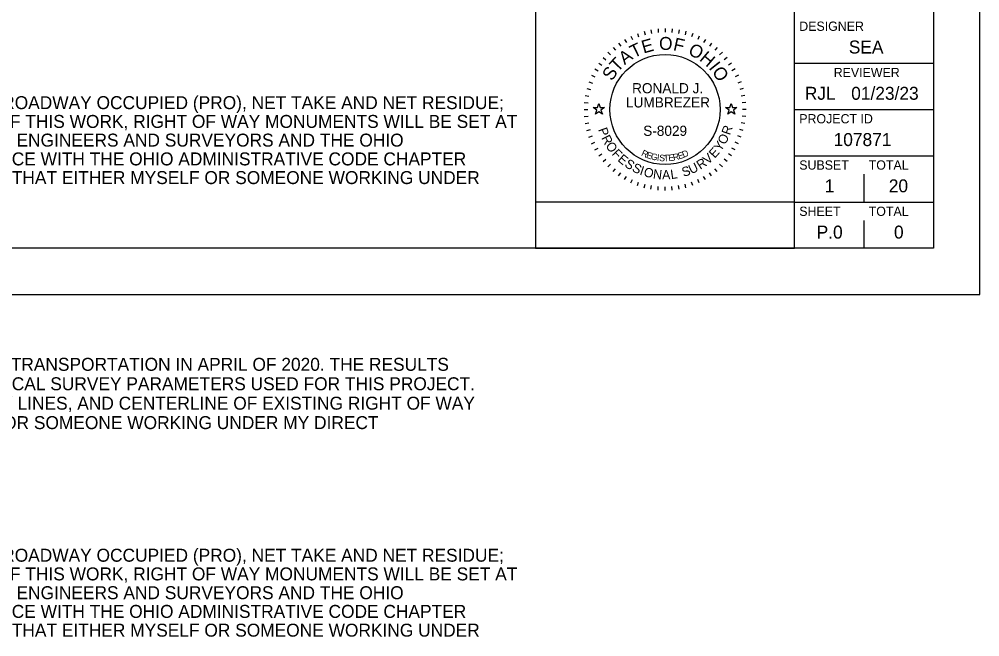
# Model space of a CAD drawing. Extents: x 0 to 39.3, y -3.9 to 22.
# Drawn here: x 23.62 to 34, y -3.7 to 2.98 of the extents above; entities that cross this region are included whole.
import ezdxf

# ---------------------------------------------------------------- set-up
doc = ezdxf.new("R2010")
doc.units = 0
for name, color, linetype in [('Default', 7, 'Continuous'), ('SH_Border', 7, 'Continuous'), ('SH_Cut_Line', 7, 'Continuous'), ('SH_Data', 7, 'Continuous'), ('SH_Text', 7, 'Continuous')]:
    doc.layers.add(name, color=color, linetype=linetype)

msp = doc.modelspace()

# ---------------------------------------------------------------- linework, layer by layer
at = {"layer": 'Default'}
for points in [[(29.824, 2.02), (29.871, 2.02), (29.885, 2.065), (29.899, 2.02), (29.946, 2.02), (29.908, 1.992), (29.923, 1.948), (29.885, 1.975), (29.847, 1.948), (29.862, 1.992)], [(31.254, 2.02), (31.301, 2.02), (31.315, 2.065), (31.329, 2.02), (31.376, 2.02), (31.338, 1.992), (31.353, 1.948), (31.315, 1.975), (31.277, 1.948), (31.292, 1.992)]]:
    msp.add_lwpolyline(points, close=True, dxfattribs=at)
at = {"layer": 'SH_Border'}
for p, q in [((32, 0.5), (32, 21.5)), ((32, 2.5), (33.5, 2.5)), ((32, 2), (33.5, 2)), ((32, 1.5), (33.5, 1.5)), ((32, 1), (33.5, 1))]:
    msp.add_line(p, q, dxfattribs=at)
msp.add_lwpolyline([(1.5, 21.5), (33.5, 21.5), (33.5, 0.5), (1.5, 0.5)], close=True, dxfattribs=at)
at = {"layer": 'SH_Cut_Line'}
msp.add_lwpolyline([(0, 0), (34, 0), (34, 22), (0, 22)], close=True, dxfattribs=at)
at = {"layer": 'SH_Data'}
for p, q in [((29.2, 3.75), (29.2, 0.5)), ((32, 0.5), (32, 3.75)), ((30.301, 2.822), (30.314, 2.785)), ((30.374, 2.845), (30.384, 2.807)), ((30.448, 2.862), (30.455, 2.822)), ((30.524, 2.872), (30.527, 2.832)), ((30.6, 2.875), (30.6, 2.835)), ((30.676, 2.872), (30.673, 2.832)), ((30.752, 2.862), (30.745, 2.822)), ((30.826, 2.845), (30.816, 2.807)), ((30.899, 2.822), (30.886, 2.785)), ((30.098, 2.717), (30.121, 2.684)), ((30.163, 2.758), (30.183, 2.723)), ((30.23, 2.793), (30.247, 2.757)), ((30.97, 2.793), (30.953, 2.757)), ((31.037, 2.758), (31.017, 2.723)), ((31.102, 2.717), (31.079, 2.684)), ((29.981, 2.619), (30.01, 2.59)), ((30.038, 2.67), (30.063, 2.64)), ((31.162, 2.67), (31.137, 2.64)), ((31.219, 2.619), (31.19, 2.59)), ((29.883, 2.502), (29.916, 2.479)), ((29.93, 2.562), (29.96, 2.537)), ((31.27, 2.562), (31.24, 2.537)), ((31.317, 2.502), (31.284, 2.479)), ((29.842, 2.438), (29.877, 2.418)), ((31.358, 2.438), (31.323, 2.418)), ((29.778, 2.299), (29.815, 2.286)), ((29.807, 2.37), (29.843, 2.353)), ((31.393, 2.37), (31.357, 2.353)), ((31.422, 2.299), (31.385, 2.286)), ((29.755, 2.226), (29.793, 2.216)), ((31.445, 2.226), (31.407, 2.216)), ((29.728, 2.076), (29.768, 2.073)), ((29.738, 2.152), (29.778, 2.145)), ((31.462, 2.152), (31.422, 2.145)), ((31.472, 2.076), (31.432, 2.073)), ((29.725, 2), (29.765, 2)), ((31.475, 2), (31.435, 2)), ((29.728, 1.924), (29.768, 1.927)), ((31.472, 1.924), (31.432, 1.927)), ((29.738, 1.848), (29.778, 1.855)), ((29.755, 1.774), (29.793, 1.784)), ((31.445, 1.774), (31.407, 1.784)), ((31.462, 1.848), (31.422, 1.855)), ((29.778, 1.701), (29.815, 1.714)), ((31.422, 1.701), (31.385, 1.714)), ((29.807, 1.63), (29.843, 1.647)), ((29.842, 1.563), (29.877, 1.583)), ((31.358, 1.563), (31.323, 1.583)), ((31.393, 1.63), (31.357, 1.647)), ((29.883, 1.498), (29.916, 1.521)), ((29.93, 1.438), (29.96, 1.463)), ((31.27, 1.438), (31.24, 1.463)), ((31.317, 1.498), (31.284, 1.521)), ((29.981, 1.381), (30.01, 1.41)), ((30.038, 1.33), (30.063, 1.36)), ((31.162, 1.33), (31.137, 1.36)), ((31.219, 1.381), (31.19, 1.41)), ((30.098, 1.283), (30.121, 1.316)), ((30.163, 1.242), (30.183, 1.277)), ((31.037, 1.242), (31.017, 1.277)), ((31.102, 1.283), (31.079, 1.316)), ((32.75, 1), (32.75, 1.3)), ((30.23, 1.207), (30.247, 1.243)), ((30.301, 1.178), (30.314, 1.215)), ((30.374, 1.155), (30.384, 1.193)), ((30.448, 1.138), (30.455, 1.178)), ((30.524, 1.128), (30.527, 1.168)), ((30.6, 1.125), (30.6, 1.165)), ((30.676, 1.128), (30.673, 1.168)), ((30.752, 1.138), (30.745, 1.178)), ((30.826, 1.155), (30.816, 1.193)), ((30.899, 1.178), (30.886, 1.215)), ((30.97, 1.207), (30.953, 1.243)), ((32.75, 0.5), (32.75, 0.8)), ((32.375, 0.675), (32.375, 0.675)), ((32, 0.5), (29.2, 0.5))]:
    msp.add_line(p, q, dxfattribs=at)
msp.add_lwpolyline([(32, 0.5), (32, 1), (29.2, 1), (29.2, 0.5)], close=True, dxfattribs=at)
msp.add_circle((30.6, 2), 0.595, dxfattribs=at)

# ---------------------------------------------------------------- texts
for s, height, p in [('DESIGNER', 0.1, (32.05, 2.85)), ('SEA', 0.14, (32.585, 2.605)), ('REVIEWER', 0.1, (32.422, 2.35)), ('RONALD J.', 0.11, (30.244, 2.175)), ('RJL', 0.14, (32.11, 2.105)), ('01/23/23', 0.14, (32.611, 2.105)), ('LUMBREZER', 0.11, (30.178, 2.022)), ('PROJECT ID', 0.1, (32.05, 1.85)), ('S-8029', 0.11, (30.364, 1.715)), ('107871', 0.14, (32.421, 1.605)), ('SUBSET', 0.1, (32.05, 1.35)), ('TOTAL', 0.1, (32.8, 1.35)), ('20', 0.14, (33.017, 1.105)), ('1', 0.14, (32.325, 1.105)), ('SHEET', 0.1, (32.05, 0.85)), ('TOTAL', 0.1, (32.8, 0.85)), ('P.0', 0.14, (32.238, 0.605)), ('0', 0.14, (33.073, 0.605))]:
    msp.add_text(s, height=height, dxfattribs=at).set_placement(p)
for s, height, rotation, p in [('T', 0.14, 25.7167, (30.262, 2.552)), ('E', 0.14, 15.7571, (30.368, 2.604)), ('O', 0.14, 359.7812, (30.535, 2.644)), ('F', 0.14, 347.4362, (30.681, 2.642)), ('O', 0.14, 332.2586, (30.84, 2.602)), ('A', 0.14, 36.4747, (30.163, 2.478)), ('H', 0.14, 319.9136, (30.963, 2.536)), ('T', 0.14, 46.4344, (30.088, 2.396)), ('I', 0.14, 308.367, (31.066, 2.448)), ('S', 0.14, 57.1924, (30.028, 2.301)), ('O', 0.14, 303.1491, (31.102, 2.409)), ('P', 0.1, 289.7431, (29.875, 1.784)), ('R', 0.1, 70.983, (31.301, 1.717)), ('R', 0.1, 296.9802, (29.909, 1.693)), ('Y', 0.1, 55.5058, (31.2, 1.54)), ('O', 0.1, 62.7428, (31.25, 1.613)), ('O', 0.1, 304.7158, (29.953, 1.608)), ('F', 0.1, 312.956, (30.019, 1.516)), ('R', 0.07, 334.487, (30.337, 1.505)), ('D', 0.07, 23.3052, (30.801, 1.477)), ('E', 0.1, 48.2687, (31.137, 1.467)), ('E', 0.1, 319.6885, (30.081, 1.45)), ('S', 0.1, 326.9255, (30.155, 1.389)), ('E', 0.07, 341.04, (30.391, 1.48)), ('G', 0.07, 347.4752, (30.441, 1.462)), ('I', 0.07, 353.7858, (30.509, 1.447)), ('S', 0.07, 356.8926, (30.536, 1.443)), ('T', 0.07, 3.0061, (30.586, 1.439)), ('E', 0.07, 6.0117, (30.639, 1.441)), ('R', 0.07, 11.9184, (30.692, 1.447)), ('E', 0.07, 17.6836, (30.75, 1.46)), ('R', 0.1, 33.296, (30.981, 1.347)), ('V', 0.1, 41.0316, (31.061, 1.401)), ('S', 0.1, 334.1626, (30.236, 1.337)), ('I', 0.1, 341.3997, (30.319, 1.298)), ('O', 0.1, 345.1351, (30.362, 1.282)), ('N', 0.1, 353.3752, (30.466, 1.255)), ('L', 0.1, 8.3479, (30.666, 1.247)), ('S', 0.1, 18.3234, (30.8, 1.271)), ('U', 0.1, 25.5604, (30.883, 1.299)), ('A', 0.1, 1.1108, (30.569, 1.244))]:
    msp.add_text(s, height=height, rotation=rotation, dxfattribs=at).set_placement(p)
at = {"layer": 'SH_Text'}
for s, p in [('HAVE ESTABLISHED THE PROPOSED BOUNDARY LINES, CALCULATED THE GROSS TAKE, PRESENT ROADWAY OCCUPIED (PRO), NET TAKE AND NET RESIDUE;', (14.264, 2.004)), ('AS WELL AS PREPARED THE LEGAL DESCRIPTIONS NECESSARY TO ACQUIRE THE PARCELS AS SHOWN HEREIN.  AS A PART OF THIS WORK, RIGHT OF WAY MONUMENTS WILL BE SET AT', (11.851, 1.801)), ('THE LOCATIONS SHOWN HEREIN PER THE MEMORANDUM OF UNDERSTANDING BETWEEN THE BOARD OF REGISTRATION FOR ENGINEERS AND SURVEYORS AND THE OHIO', (11.851, 1.599)), ('DEPARTMENT OF TRANSPORTATION DATED 9-22-2010. ALL OF MY WORK CONTAINED HEREIN WAS CONDUCTED IN ACCORDANCE WITH THE OHIO ADMINISTRATIVE CODE CHAPTER', (11.851, 1.396)), ('4733-37 STANDARDS FOR BOUNDARY SURVEYS UNLESS SO NOTED.  THE WORDS “I” AND “MY” AS USED HEREIN ARE TO MEAN THAT EITHER MYSELF OR SOMEONE WORKING UNDER', (11.851, 1.194)), ('I, JEFFREY C. THOMPSON, P. S. HAVE CONDUCTED A SURVEY OF THE EXISTING CONDITIONS FOR THE OHIO DEPARTMENT OF TRANSPORTATION IN APRIL OF 2020. THE RESULTS', (11.851, -0.824)), ('OF THAT SURVEY ARE CONTAINED HEREIN.  SEE THE AFFIXED SURVEY PARAMETERS NOTE FOR THE HORIZONTAL AND VERTICAL SURVEY PARAMETERS USED FOR THIS PROJECT.', (11.851, -1.034)), ('AS A PART OF THIS PROJECT I HAVE REESTABLISHED THE LOCATIONS OF THE EXISTING RIGHT OF WAY, EXISTING BOUNDARY LINES, AND CENTERLINE OF EXISTING RIGHT OF WAY', (11.851, -1.244)), ('FOR PROPERTY TAKES CONTAINED HEREIN.  THE WORDS “I” AND “MY” AS USED HEREIN ARE TO MEAN THAT EITHER MYSELF OR SOMEONE WORKING UNDER MY DIRECT', (11.851, -1.454)), ('HAVE ESTABLISHED THE PROPOSED BOUNDARY LINES, CALCULATED THE GROSS TAKE, PRESENT ROADWAY OCCUPIED (PRO), NET TAKE AND NET RESIDUE;', (14.264, -2.887)), ('AS WELL AS PREPARED THE LEGAL DESCRIPTIONS NECESSARY TO ACQUIRE THE PARCELS AS SHOWN HEREIN.  AS A PART OF THIS WORK, RIGHT OF WAY MONUMENTS WILL BE SET AT', (11.851, -3.089)), ('THE LOCATIONS SHOWN HEREIN PER THE MEMORANDUM OF UNDERSTANDING BETWEEN THE BOARD OF REGISTRATION FOR ENGINEERS AND SURVEYORS AND THE OHIO', (11.851, -3.292)), ('DEPARTMENT OF TRANSPORTATION DATED 9-22-2010. ALL OF MY WORK CONTAINED HEREIN WAS CONDUCTED IN ACCORDANCE WITH THE OHIO ADMINISTRATIVE CODE CHAPTER', (11.851, -3.494)), ('4733-37 STANDARDS FOR BOUNDARY SURVEYS UNLESS SO NOTED.  THE WORDS “I” AND “MY” AS USED HEREIN ARE TO MEAN THAT EITHER MYSELF OR SOMEONE WORKING UNDER', (11.851, -3.697))]:
    msp.add_text(s, height=0.14, dxfattribs=at).set_placement(p)

doc.saveas('drawing.dxf')
